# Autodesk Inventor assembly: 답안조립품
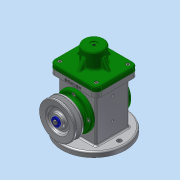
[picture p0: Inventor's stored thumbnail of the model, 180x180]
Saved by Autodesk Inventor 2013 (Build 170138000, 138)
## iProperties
Created: 2018-10
Part Number: 답안조립품
Document SubType Name: Assembly
Designer: dgall
Author: dgall
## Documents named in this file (18)
- C:\Users\dgall\Desktop\481007V1066\답안조립품.iam
- C:\Users\dgall\Desktop\481007V1066\본체.ipt
- C:\Users\dgall\Desktop\481007V1066\E-링.ipt
- C:\Users\dgall\Desktop\481007V1066\V-벨트풀리.ipt
- C:\Users\dgall\Desktop\481007V1066\덮개.ipt
- C:\Users\dgall\Desktop\481007V1066\뒤커버.ipt
- C:\Users\dgall\Desktop\481007V1066\링크.ipt
- C:\Users\dgall\Desktop\481007V1066\베어링 17 x 40 x 12.ipt
- C:\Users\dgall\Desktop\481007V1066\볼트 M4 x 8.ipt
- C:\Users\dgall\Desktop\481007V1066\볼트 M4 x 10.ipt
- C:\Users\dgall\Desktop\481007V1066\슬라이더.ipt
- C:\Users\dgall\Desktop\481007V1066\앞커버.ipt
- C:\Users\dgall\Desktop\481007V1066\오일 실 17 30 8.ipt
- C:\Users\dgall\Desktop\481007V1066\와셔 4x16.ipt
- C:\Users\dgall\Desktop\481007V1066\클레비스 핀 6 x 22.ipt
- 클레비스 핀 6 x 22.ipt
- C:\Users\dgall\Desktop\481007V1066\키 4 x 4 x 12.ipt
- C:\Users\dgall\Desktop\481007V1066\편심축.ipt
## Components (2 placed, 2 different names)
1. E-링:1
2. V-벨트풀리:1
